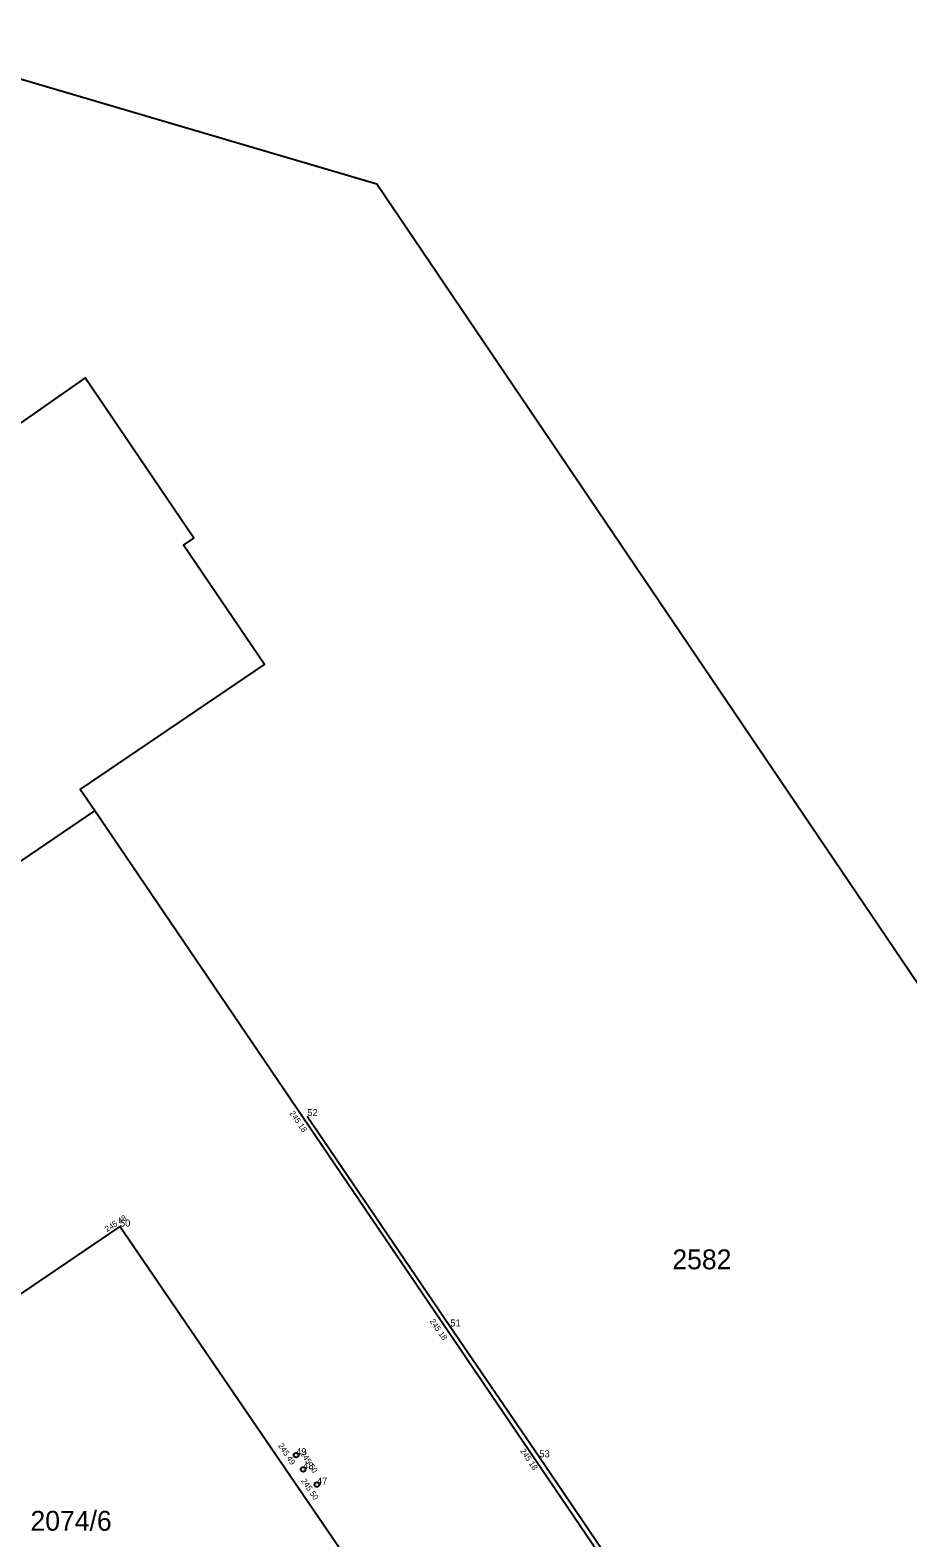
# Model space of a CAD drawing. Extents: x -675895 to -675697, y -1071173 to -1070976.
# Drawn here: x -675824.8 to -675787.3, y -1071049.1 to -1070984.5 of the extents above; entities that cross this region are included whole.
import ezdxf

# ---------------------------------------------------------------- set-up
doc = ezdxf.new("R2010")
doc.units = 0
for name, color, linetype in [('Vrstva 1', 7, 'Continuous'), ('Vrstva 2', 7, 'Continuous'), ('Vrstva 3', 7, 'Continuous'), ('Vrstva 4', 7, 'Continuous'), ('Vrstva 50', 7, 'Continuous'), ('Vrstva 6', 7, 'Continuous'), ('Vrstva 7', 7, 'Continuous')]:
    doc.layers.add(name, color=color, linetype=linetype)

msp = doc.modelspace()

# ---------------------------------------------------------------- linework, layer by layer
at = {"layer": 'Vrstva 1'}
for p, q in [((-675812.98, -1071031.02), (-675812.98, -1071031.02)), ((-675821, -1071035.75), (-675821, -1071035.75)), ((-675806.86, -1071040.03), (-675806.86, -1071040.03)), ((-675813.46, -1071045.54), (-675813.46, -1071045.54)), ((-675803.05, -1071045.63), (-675803.05, -1071045.63)), ((-675813.16, -1071046.15), (-675813.16, -1071046.15)), ((-675812.57, -1071046.8), (-675812.57, -1071046.8))]:
    msp.add_line(p, q, dxfattribs=at)
at = {"layer": 'Vrstva 4'}
msp.add_lwpolyline([(-675812.98, -1071031.02), (-675806.86, -1071040.03), (-675803.05, -1071045.63), (-675783.85, -1071073.91), (-675766.881, -1071098.872)], dxfattribs=at)
at = {"layer": 'Vrstva 50'}
msp.add_line((-675794.05, -1071059.25), (-675822.08, -1071017.95), dxfattribs=at)
for points in [[(-675833.97, -1070985.62), (-675832.35, -1070984.52), (-675810.01, -1070991.1), (-675746.78, -1071084.6)], [(-675822.08, -1071017.95), (-675822.7, -1071017.04), (-675814.81, -1071011.69), (-675818.28, -1071006.58), (-675817.83, -1071006.27), (-675822.48, -1070999.41), (-675838.87, -1071010.86), (-675834.3, -1071017.57), (-675833.36, -1071016.94), (-675830.82, -1071020.68)], [(-675830.82, -1071020.68), (-675829.32, -1071022.88), (-675822.08, -1071017.95)]]:
    msp.add_lwpolyline(points, dxfattribs=at)
at = {"layer": 'Vrstva 6'}
for p, q in [((-675821, -1071035.75), (-675836.59, -1071046.32)), ((-675810.836, -1071050.641), (-675821, -1071035.75))]:
    msp.add_line(p, q, dxfattribs=at)
at = {"layer": 'Vrstva 7'}
for centre in [(-675813.46, -1071045.54), (-675813.16, -1071046.15), (-675812.57, -1071046.8)]:
    msp.add_circle(centre, 0.1, dxfattribs=at)

# ---------------------------------------------------------------- texts
at = {"layer": 'Vrstva 2'}
for s, p in [('52', (-675812.98, -1071031.02)), ('50', (-675821, -1071035.75)), ('51', (-675806.86, -1071040.03)), ('49', (-675813.46, -1071045.54)), ('53', (-675803.05, -1071045.63)), ('48', (-675813.16, -1071046.15)), ('47', (-675812.57, -1071046.8))]:
    msp.add_text(s, height=0.3, dxfattribs=at).set_placement(p)
at = {"layer": 'Vrstva 3'}
for s, rotation, p in [('245 18 ', 304.54144, (-675813.756, -1071030.9)), ('245 48 ', 32.27116, (-675821.55, -1071035.99)), ('245 18 ', 304.69515, (-675807.755, -1071039.809)), ('245 49 ', 303.05145, (-675814.238, -1071045.131)), ('245 50 ', 303.53869, (-675813.293, -1071045.479)), ('245 18 ', 304.06888, (-675803.879, -1071045.363)), ('245 50 ', 304.00188, (-675813.258, -1071046.639))]:
    msp.add_text(s, height=0.25, rotation=rotation, dxfattribs=at).set_placement(p)
at = {"layer": 'Vrstva 50'}
for s, p in [('2582', (-675797.357, -1071037.58)), ('2074/6', (-675824.828, -1071048.775))]:
    msp.add_text(s, height=0.85, dxfattribs=at).set_placement(p)

doc.saveas('drawing.dxf')
